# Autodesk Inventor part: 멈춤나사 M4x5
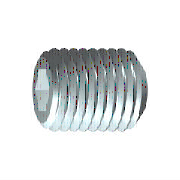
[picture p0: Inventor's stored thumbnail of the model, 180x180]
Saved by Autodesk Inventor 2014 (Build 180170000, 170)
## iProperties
IsCustomPart: 1
Created: 2012-02
Part Number: 멈춤나사 M4x5
Material: 강철, 연강
Description: 6각 소켓 머리 없는 멈춤 나사
Document SubType Name: Modeling
Standard: KS B 1028
Designer: mduedu
Standards Organization: KS
Language: ko-KR
Size Designation: 납작점M4x5
Categories: <MemberInstance><Categories><Category DisplayName="조임쇠" InternalName="e4da775c-781d-43d5-af7c-5136215cf5a6" Mnemonic="FSTN"><Category DisplayName="볼트" InternalN
Density: 1 g/cm^3
Appearance: Steel
Author: mduedu
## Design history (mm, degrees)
sketch "스케치1"
  geometry: L1 (0, 0)-(1.833, 0); L2 (5, 1.155)-(5, 2); L3 (5, 2)-(0, 2); L4 (5, 1.155)-(2.5, 1.155); L5 (2.5, 1.155)-(1.833, 0); L6 (0, -0.4)-(0, 2.4) reference; L7 (0, 2)-(0, 0)
  constraints: 13 end point, 3 parallel, 1 collinear, 1 perpendicular, 1 point on line
  dimensions: "d0" = 2.5 distance of L2.start L4.end (= INTI); "d1" = 60 deg angle of L5 L1; "d2" = 4 diameter of L3 L1 (= NND); "d3" = 2.3094 diameter of L4 L1 (= 1.1547 x SW); "d5" = 5 distance from line of L2 L3.end (= NLG)
revolve "본체" sketch "스케치1" stored, may be unused: angle "d6" = 90 deg
sketch "스케치2"
  geometry: L1 (-0.577, 1)-(0.577, 1); L2 (0.577, 1)-(1.155, 0); L3 (1.155, 0)-(0.577, -1); L4 (0.577, -1)-(-0.577, -1); L5 (-0.577, -1)-(-1.155, 0); L6 (-1.155, 0)-(-0.577, 1); A1 r 1.155 centre (0, 0) between (-0.577, 1) and (0.577, 1) reference; 2 further points
  constraints: 12 end point, 2 point on circle, 1 coincident, 1 horizontal, 11 other
extrude "슬롯" join sketch "스케치2" taper "d9" = 0 deg; stored distance "d21" = 10
workaxis "Work Axis1"
workplane "Work Plane1"
workpoint "Work Point1"
  workaxis "Work Axis2"
body "Solid1"
chamfer "모따기1" distance "d7" = 0.42941 (= -0.5 x GD1 + 0.5 x NND); stored, may be unused: angle "d8" = 45 deg (= FAWI), second distance "d29" = 0.42941 (= -0.5 x GD1 + 0.5 x NND)
feature "스레드" dims "d11" = 5 (= NLG), "d12" = 0
chamfer "모따기2" distance "d13" = 0.42941 (= -0.5 x GD1 + 0.5 x NND); stored, may be unused: angle "d14" = 45 deg (= FAWI), second distance "d30" = 0.42941 (= -0.5 x GD1 + 0.5 x NND)
other parameters: "NND" = 4 [user parameter; used in 5 equation terms], "NLG" = 5 [user parameter; used in 2 equation terms], "INTI" = 2.5 [user parameter; used in 1 equation term], "FAWI" = 45 deg [user parameter; used in 2 equation terms], "SW" = 2 [user parameter; used in 2 equation terms], "GD1" = 3.14117 (= THREADDIA - 1.2269 x PTC) [user parameter; used in 4 equation terms], "d4" = 0, "FAWI1" = 45 deg [user parameter], "d15" = 0, "d31" = 0, "GUL" = 0.42941 (= 0.61345 x PTC) [user parameter], "SPD" = 2.5 [user parameter], "TPU" = 14.28571 (computed from PTC) [user parameter], "TOA" = 30 deg [user parameter], "THREADDIA" = 4 [user parameter; used in 1 equation term], "PTC" = 0.7 [user parameter; used in 4 equation terms], "GAL" = 0.42941 (= 0.61345 x PTC) [user parameter], "E0" = 2.31 (= 1.155 x SW) [user parameter]
